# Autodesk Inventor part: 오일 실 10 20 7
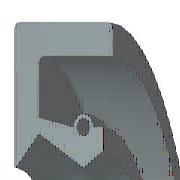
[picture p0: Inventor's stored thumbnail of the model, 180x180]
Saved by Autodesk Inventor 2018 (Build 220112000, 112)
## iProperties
IsCustomPart: 1
Created: 2012-02
Part Number: 오일 실 10 20 7
Material: 고무
Description: 오일-실
Document SubType Name: Modeling
Standard: KS B 2804
Designer: mduedu
Standards Organization: KS
Language: ko-KR
Size Designation: D - 10 20 7
Categories: <MemberInstance><Categories><Category DisplayName="샤프트 부품" InternalName="7f7aeb1f-a693-4053-b835-cee3144e0d98" Mnemonic="SHFT"><Category DisplayName="실링" Intern
Density: 0.93 g/cm^3
Appearance: 고무 - 검은색 - 버전 1.1
Author: mduedu
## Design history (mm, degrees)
revolve "본체" stored, may be unused: angle "d17" = 90 deg
revolve "스프링1" stored, may be unused: angle "d18" = 90 deg
body "Solid1"
sketch "스케치1"
  geometry: L1 (0, 10)-(7, 10); L2 (7, 8.25)-(1.75, 8.25); L3 (1.75, 6.75)-(4.9, 5); L4 (4.9, 5)-(0, 5); L5 (0, 0)-(9.586, 0) reference; L6 (4.9, 5)-(6.3, 5.875); L7 (0, 18)-(0, -3) reference; L8 (-1.941, 0)-(11.507, 0) reference; L9 (4.2, 7.1)-(1.75, 7.59); L10 (1.75, 7.59)-(1.75, 8.25); L11 (0, 10)-(0, 5.088); L12 (4.9, 5)-(0, 5); L13 (1.75, 6.75)-(0.152, 5.028); L14 (7, 10)-(7, 8.25); L15 (5.6, 7.1)-(6.3, 7.1); L16 (6.3, 7.1)-(6.3, 5.875); C1 r 0.455 at (4.9, 7.1); A1 r 0.7 centre (4.9, 7.1) between (5.6, 7.1) and (4.2, 7.1); A2 r 0.088 centre (0.088, 5.088) between (0, 5.088) and (0.152, 5.028); 1 further point
  constraints: 28 end point, 5 horizontal alignment, 5 point on line, 4 point on circle, 4 vertical alignment, 3 centre point, 3 tangent, 2 collinear, 2 horizontal, 2 perpendicular, 1 coincident, 1 parallel
  dimensions: "d0" = 20 diameter of L1 L5 (= SD2); "d1" = 1.75 distance of L1.end L2.start (= SD); "d2" = 0.91 diameter of C1 (= SPDI); "d3" = 1.4 diameter of A1 (= SPDA); "d4" = 10 diameter of L3.end L5 (= NND); "d5" = 13.5 diameter of L3.start L5 (= TKDM); "d7" = 15.18 diameter of L9.end L5 (= TKDM + 0.24 x SWDT); "d8" = 1.75 distance between parallel lines of L11 L10 (= SD); "d9" = 4.9 distance from line of L11 C1.centre (= SPDST); "d10" = 14.2 diameter of C1.centre L5 (= HLDM); "d11" = 0.0875 radius of A2 (= 0.25 x LAB); "d12" = 6.3 distance between parallel lines of L11 L16 (= SDI); "d13" = 11.75 diameter of L6.end L5 (= ABDM); "d14" = 7 distance from line of L11 L1.end (= SWDT)
fillet "모깎기1" dims "d6" = 0.3 (= RR)
other parameters: "SD2" = 20 [user parameter; used in 1 equation term], "SWDT" = 7 [user parameter; used in 2 equation terms], "RR" = 0.3 [user parameter; used in 1 equation term], "SD" = 1.75 [user parameter; used in 2 equation terms], "NND" = 10 [user parameter; used in 1 equation term], "SPDA" = 1.4 [user parameter; used in 1 equation term], "SPDI" = 0.91 [user parameter; used in 1 equation term], "TKDM" = 13.5 [user parameter; used in 2 equation terms], "HLDM" = 14.2 [user parameter; used in 1 equation term], "ABDM" = 11.75 [user parameter; used in 1 equation term], "SDI" = 6.3 [user parameter; used in 1 equation term], "SPDST" = 4.9 [user parameter; used in 1 equation term], "LAB" = 0.35 [user parameter; used in 1 equation term], "d15" = 0, "d16" = 0, "d19" = 0
